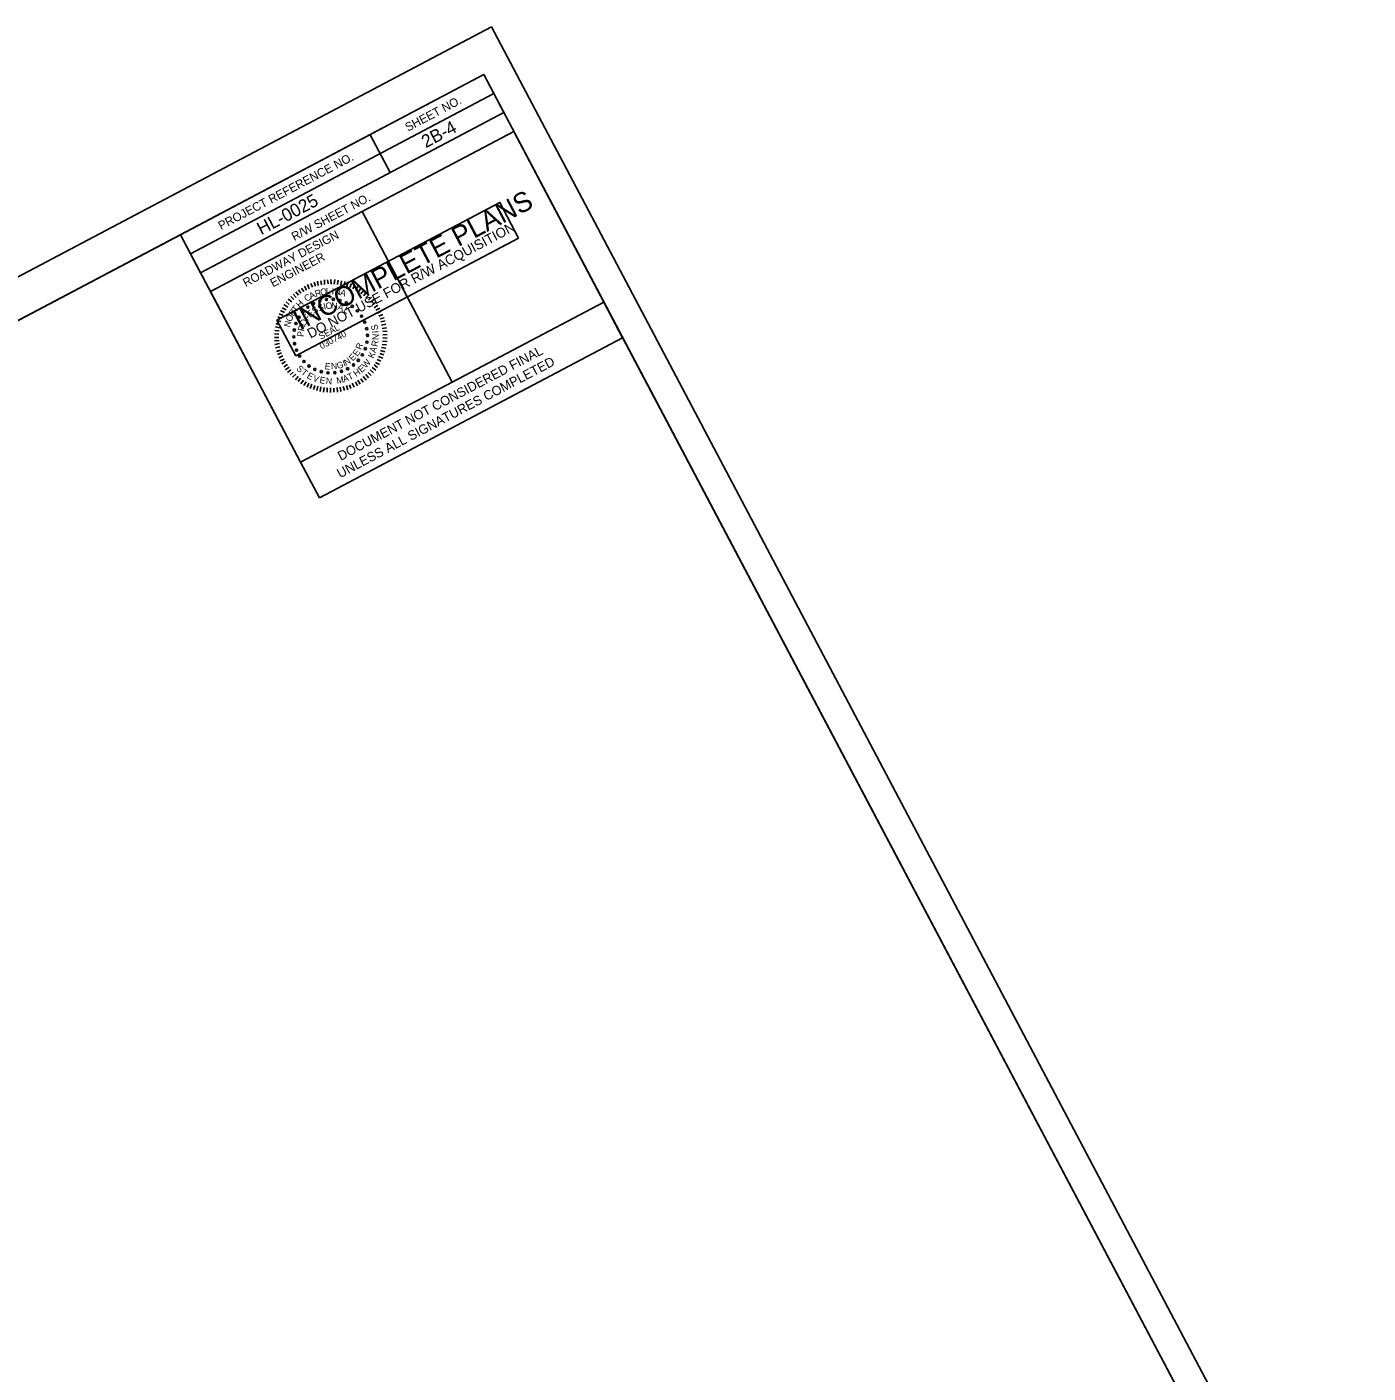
# Model space of a CAD drawing. Extents: x 1487555 to 1489555, y 497613 to 499367.
# Drawn here: x 1488773 to 1489555, y 498582 to 499367 of the extents above; entities that cross this region are included whole.
import ezdxf

# ---------------------------------------------------------------- set-up
doc = ezdxf.new("R2010")
doc.units = 0
for name, color, linetype in [('Old_Level_9', 7, 'Continuous'), ('Sheet Border Standard 30in CELL', 7, 'Continuous'), ('Sheet Data Field CELL', 7, 'Continuous'), ('Sheet Plan CELL', 7, 'Continuous'), ('Sheet Plot Border Outside CELL', 7, 'Continuous'), ('Sheet Sticker Exception Certification CELL', 7, 'Continuous'), ('Sheet Sticker Incomplete CELL', 7, 'Continuous')]:
    doc.layers.add(name, color=color, linetype=linetype)

msp = doc.modelspace()

# ---------------------------------------------------------------- linework, layer by layer
at = {"layer": 'Old_Level_9'}
for p, q in [((1488942.02, 499218.65), (1488942.52, 499216.2)), ((1488943.98, 499219), (1488944.48, 499216.55)), ((1488946.11, 499219.45), (1488946.17, 499216.77)), ((1488947.99, 499219.54), (1488948.27, 499217.09)), ((1488949.96, 499219.67), (1488950.02, 499216.99)), ((1488952.1, 499219.68), (1488951.8, 499217.03)), ((1488954.13, 499219.27), (1488953.73, 499216.8)), ((1488956.1, 499218.96), (1488955.62, 499216.44)), ((1488958.12, 499218.56), (1488957.55, 499216.22)), ((1488927.87, 499211.18), (1488929.65, 499209.29)), ((1488929.36, 499212.42), (1488930.92, 499210.53)), ((1488931.08, 499213.66), (1488932.38, 499211.63)), ((1488932.71, 499214.64), (1488934.1, 499212.66)), ((1488934.48, 499215.8), (1488935.69, 499213.5)), ((1488936.33, 499216.78), (1488937.28, 499214.34)), ((1488938.15, 499217.4), (1488939.1, 499215.18)), ((1488940.15, 499218.11), (1488940.83, 499215.76)), ((1488959.97, 499218.06), (1488959.26, 499215.54)), ((1488961.95, 499217.3), (1488961.02, 499215)), ((1488963.85, 499216.49), (1488962.65, 499214.27)), ((1488965.57, 499215.59), (1488964.37, 499213.37)), ((1488967.34, 499214.6), (1488966, 499212.42)), ((1488969.06, 499213.48), (1488967.45, 499211.38)), ((1488970.56, 499212.35), (1488969.18, 499210.26)), ((1488972.25, 499210.86), (1488970.32, 499208.94)), ((1488921.42, 499203.25), (1488923.78, 499202.01)), ((1488922.54, 499205.2), (1488924.73, 499203.64)), ((1488923.76, 499206.75), (1488925.63, 499205.13)), ((1488924.89, 499208.25), (1488927.07, 499206.69)), ((1488926.47, 499209.76), (1488928.21, 499207.96)), ((1488973.67, 499209.46), (1488971.78, 499207.68)), ((1488975, 499208.02), (1488973.02, 499206.41)), ((1488976.15, 499206.48), (1488974.26, 499204.91)), ((1488977.31, 499204.71), (1488975.15, 499203.23)), ((1488978.38, 499202.9), (1488976.16, 499201.74)), ((1488918.32, 499195.85), (1488920.71, 499195.18)), ((1488918.86, 499197.83), (1488921.16, 499196.89)), ((1488919.67, 499199.72), (1488922.06, 499198.61)), ((1488920.52, 499201.53), (1488922.78, 499200.46)), ((1488979.26, 499201.22), (1488977.05, 499200.05)), ((1488980.15, 499199.32), (1488977.94, 499198.37)), ((1488980.96, 499197.37), (1488978.6, 499196.69)), ((1488981.58, 499195.55), (1488979.04, 499195)), ((1488916.93, 499187.99), (1488919.48, 499187.86)), ((1488917.16, 499189.91), (1488919.71, 499189.79)), ((1488917.51, 499192.03), (1488919.94, 499191.5)), ((1488917.74, 499193.95), (1488920.21, 499193.34)), ((1488982.03, 499193.63), (1488979.49, 499193.09)), ((1488982.43, 499191.59), (1488979.71, 499191.17)), ((1488982.66, 499189.44), (1488980.15, 499189.48)), ((1488982.74, 499187.57), (1488980.28, 499187.51)), ((1488916.93, 499185.84), (1488919.62, 499185.9)), ((1488917.07, 499183.87), (1488919.66, 499184.11)), ((1488917.25, 499181.82), (1488919.92, 499182.33)), ((1488917.6, 499179.86), (1488920.14, 499180.41)), ((1488981.89, 499179.54), (1488979.46, 499180.07)), ((1488982.29, 499181.56), (1488979.78, 499181.82)), ((1488982.7, 499183.58), (1488980.01, 499183.75)), ((1488982.74, 499185.42), (1488980.15, 499185.63)), ((1488918.14, 499177.77), (1488920.59, 499178.49)), ((1488918.76, 499175.95), (1488921.11, 499176.85)), ((1488919.57, 499174), (1488921.91, 499175.12)), ((1488920.37, 499172.27), (1488922.67, 499173.26)), ((1488921.35, 499170.41), (1488923.46, 499171.76)), ((1488978.3, 499170.07), (1488975.94, 499171.31)), ((1488979.11, 499171.96), (1488976.85, 499173.03)), ((1488980.1, 499173.73), (1488977.61, 499174.79)), ((1488980.77, 499175.67), (1488978.51, 499176.51)), ((1488981.4, 499177.47), (1488978.92, 499178.31)), ((1488922.37, 499168.69), (1488924.53, 499170.17)), ((1488923.48, 499167.02), (1488925.5, 499168.54)), ((1488924.68, 499165.39), (1488926.61, 499167.09)), ((1488926.1, 499163.99), (1488927.94, 499165.64)), ((1488927.6, 499162.64), (1488929.4, 499164.38)), ((1488971.85, 499162.36), (1488970.2, 499164.21)), ((1488973.34, 499163.61), (1488971.69, 499165.45)), ((1488974.78, 499165.16), (1488972.73, 499166.9)), ((1488976.09, 499166.75), (1488974, 499168.36)), ((1488977.17, 499168.34), (1488975.13, 499169.86)), ((1488929.24, 499161.24), (1488930.72, 499163.15)), ((1488930.75, 499160.11), (1488932.18, 499162.11)), ((1488932.43, 499158.85), (1488933.9, 499160.99)), ((1488934.06, 499157.9), (1488935.4, 499160.08)), ((1488936.05, 499156.92), (1488937.07, 499159.27)), ((1488937.86, 499156.06), (1488938.7, 499158.54)), ((1488939.66, 499155.43), (1488940.55, 499157.82)), ((1488941.73, 499154.94), (1488942.26, 499157.37)), ((1488943.57, 499154.45), (1488944.01, 499157.05)), ((1488945.6, 499154.04), (1488945.94, 499156.6)), ((1488947.7, 499153.91), (1488947.82, 499156.46)), ((1488949.67, 499153.82), (1488949.66, 499156.42)), ((1488951.68, 499153.87), (1488951.63, 499156.32)), ((1488953.74, 499154.05), (1488953.5, 499156.63)), ((1488955.74, 499154.31), (1488955.33, 499156.81)), ((1488957.79, 499154.94), (1488957.11, 499157.3)), ((1488959.7, 499155.39), (1488958.98, 499157.83)), ((1488961.52, 499156.01), (1488960.67, 499158.27)), ((1488963.47, 499156.81), (1488962.35, 499159.16)), ((1488965.38, 499157.7), (1488964.21, 499159.91)), ((1488967.01, 499158.68), (1488965.62, 499160.88)), ((1488968.69, 499159.79), (1488967.3, 499161.77)), ((1488970.4, 499161.04), (1488968.79, 499163.01))]:
    msp.add_line(p, q, dxfattribs=at)
for centre in [(1488936.47, 499203.55), (1488939.8, 499205.7), (1488943.47, 499207.21), (1488947.35, 499208.01), (1488951.32, 499208.09), (1488955.23, 499207.44), (1488958.95, 499206.08), (1488962.37, 499204.06), (1488931.27, 499197.61), (1488933.59, 499200.82), (1488965.35, 499201.45), (1488967.8, 499198.33), (1488969.64, 499194.82), (1488928.56, 499190.19), (1488929.57, 499194.02), (1488970.8, 499191.03), (1488971.24, 499187.09), (1488928.28, 499186.23), (1488928.72, 499182.29), (1488969.95, 499179.3), (1488970.96, 499183.13), (1488929.88, 499178.5), (1488931.72, 499174.99), (1488934.17, 499171.87), (1488965.93, 499172.5), (1488968.25, 499175.72), (1488937.15, 499169.26), (1488940.57, 499167.24), (1488944.29, 499165.88), (1488948.2, 499165.23), (1488952.17, 499165.31), (1488956.05, 499166.11), (1488959.72, 499167.62), (1488963.05, 499169.77)]:
    msp.add_circle(centre, 0.63, dxfattribs=at)
at = {"layer": 'Sheet Border Standard 30in CELL'}
msp.add_line((1488873.82, 499223.66), (1488879.66, 499212.6), dxfattribs=at)
at = {"layer": 'Sheet Plan CELL'}
for p, q in [((1488867.98, 499234.72), (1489044.89, 499328.12)), ((1488873.85, 499223.64), (1489050.73, 499317.06)), ((1488873.85, 499223.64), (1489050.73, 499317.06)), ((1488972.71, 499304.13), (1488984.43, 499282.05)), ((1488968.15, 499259.31), (1489020.67, 499159.87)), ((1488873.85, 499223.64), (1488879.68, 499212.6))]:
    msp.add_line(p, q, dxfattribs=at)
for points in [[(1489039.06, 499339.23), (1487712.59, 498638.82), (1488202.86, 497710.31), (1489529.32, 498410.71)], [(1488862.13, 499245.82), (1489039.06, 499339.23), (1489050.73, 499317.06), (1488873.85, 499223.64)], [(1488968.15, 499259.31), (1489056.56, 499306.01), (1489109.11, 499206.52), (1489020.69, 499159.82)], [(1488879.68, 499212.6), (1488968.15, 499259.31), (1489020.69, 499159.82), (1488932.21, 499113.13)], [(1488202.86, 497710.31), (1487712.58, 498638.79), (1488862.13, 499245.82), (1488932.21, 499113.13), (1489109.11, 499206.52), (1489529.32, 498410.71)]]:
    msp.add_lwpolyline(points, close=True, dxfattribs=at)
at = {"layer": 'Sheet Plot Border Outside CELL'}
msp.add_lwpolyline([(1488066.15, 497612.67), (1489554.86, 498398.74), (1489043.57, 499367.04), (1487554.86, 498580.97)], close=True, dxfattribs=at)
at = {"layer": 'Sheet Sticker Exception Certification CELL'}
for p, q in [((1488932.21, 499113.13), (1489109.1, 499206.53)), ((1488932.21, 499113.13), (1489109.1, 499206.53)), ((1489109.11, 499206.52), (1489120.08, 499185.74)), ((1489109.11, 499206.52), (1489120.08, 499185.74)), ((1489120.08, 499185.75), (1488943.18, 499092.35)), ((1489120.08, 499185.75), (1488943.18, 499092.35)), ((1488943.18, 499092.35), (1488932.21, 499113.13)), ((1488943.18, 499092.35), (1488932.21, 499113.13))]:
    msp.add_line(p, q, dxfattribs=at)
at = {"layer": 'Sheet Sticker Incomplete CELL'}
msp.add_lwpolyline([(1488929.42, 499175.25), (1488918.45, 499196.03), (1489048.44, 499264.67), (1489059.41, 499243.89)], close=True, dxfattribs=at)

# ---------------------------------------------------------------- texts
at = {"layer": 'Old_Level_9'}
for s, height, rotation, p in [('C', 3.78, 32.77501, (1488935.75, 499206.52)), ('A', 3.78, 25.80995, (1488938.23, 499208.05)), ('R', 3.78, 17.85665, (1488941.24, 499209.42)), ('O', 3.78, 10.92189, (1488944.04, 499210.33)), ('L', 3.78, 3.581, (1488947.11, 499210.93)), ('I', 3.78, 358.64105, (1488950.33, 499211.05)), ('N', 3.78, 352.73893, (1488951.8, 499211.04)), ('A', 3.78, 344.84016, (1488954.9, 499210.52)), ('T', 3.78, 53.27087, (1488929.68, 499200.26)), ('H', 3.78, 45.57844, (1488931.76, 499202.94)), ('S', 3.76, 32.30312, (1488940.21, 499199.37)), ('S', 3.76, 20.87655, (1488942.99, 499200.95)), ('I', 3.76, 13.31716, (1488946.01, 499202.1)), ('O', 3.76, 5.70998, (1488946.99, 499202.39)), ('N', 3.76, 355.22811, (1488949.89, 499202.67)), ('A', 3.76, 341.77886, (1488953.52, 499202.22)), ('L', 3.76, 329.3674, (1488956.9, 499200.95)), ('N', 3.78, 75.90175, (1488926.02, 499191.54)), ('O', 3.78, 67.77931, (1488926.8, 499194.78)), ('R', 3.78, 60.01054, (1488928.21, 499197.9)), ('O', 3.76, 66.08691, (1488934.91, 499192.05)), ('F', 3.76, 54.23505, (1488936.5, 499195.26)), ('E', 3.76, 44.42402, (1488937.93, 499197.26)), ('P', 3.76, 87.95873, (1488934.06, 499186.17)), ('R', 3.76, 77.58289, (1488934.26, 499189.22)), ('SEAL', 3.759, 27.83509, (1488944.06, 499184.48)), ('030740', 3.759, 27.83509, (1488944.53, 499178.9)), ('S', 3.78, 100.09298, (1488977.51, 499190.36)), ('I', 3.78, 93.88149, (1488977.68, 499188.54)), ('N', 3.78, 87.20766, (1488977.75, 499184.28)), ('E', 3.76, 54.9919, (1488965.32, 499174.52)), ('R', 3.76, 68.18435, (1488967.56, 499178.42)), ('A', 3.78, 71.35678, (1488975.89, 499176.61)), ('R', 3.78, 78.98541, (1488977.09, 499180.26)), ('G', 3.76, 15.31634, (1488953.89, 499167.47)), ('I', 3.76, 23.45968, (1488957.75, 499168.72)), ('N', 3.76, 30.96288, (1488958.81, 499169.28)), ('E', 3.76, 43.64078, (1488962.56, 499171.82)), ('W', 3.78, 49.84085, (1488970.4, 499167.57)), ('K', 3.78, 63.9761, (1488974.63, 499173.38)), ('S', 3.78, 316.0471, (1488929.46, 499167.37)), ('T', 3.78, 323.45948, (1488932.15, 499164.81)), ('E', 3.78, 331.65758, (1488935.52, 499162.43)), ('V', 3.78, 339.76489, (1488939.01, 499160.67)), ('E', 3.76, 352.70428, (1488946.1, 499167.43)), ('N', 3.76, 3.89345, (1488950.05, 499167.25)), ('A', 3.78, 18.01726, (1488957.4, 499159.72)), ('T', 3.78, 25.22168, (1488960.68, 499160.82)), ('H', 3.78, 33.84631, (1488964.58, 499162.75)), ('E', 3.78, 41.99985, (1488967.79, 499165.11)), ('E', 3.78, 348.06633, (1488942.95, 499159.4)), ('N', 3.78, 356.16408, (1488946.85, 499158.71)), ('M', 3.78, 10.17213, (1488953.48, 499158.82))]:
    msp.add_text(s, height=height, rotation=rotation, dxfattribs=at).set_placement(p)
at = {"layer": 'Sheet Data Field CELL'}
for s, p in [('2B-4', (1489005.25, 499296.22)), ('HL-0025', (1488909.26, 499245.46))]:
    msp.add_text(s, height=7.5, rotation=27.8351, dxfattribs=at).set_placement(p)
at = {"layer": 'Sheet Plan CELL'}
for s, height, p in [('SHEET NO.', 5, (1488994.8, 499305.88)), ('PROJECT REFERENCE NO.', 5.0001, (1488885.84, 499248.47)), ('R/W SHEET NO.', 5.0001, (1488928.54, 499242.13)), ('ROADWAY DESIGN', 5.0001, (1488900.22, 499215.19)), ('ENGINEER', 5, (1488916.11, 499215.05))]:
    msp.add_text(s, height=height, rotation=27.8351, dxfattribs=at).set_placement(p)
at = {"layer": 'Sheet Sticker Exception Certification CELL'}
for s, p in [('DOCUMENT NOT CONSIDERED FINAL', (1488955.67, 499113.82)), ('DOCUMENT NOT CONSIDERED FINAL', (1488955.67, 499113.82)), ('UNLESS ALL SIGNATURES COMPLETED', (1488955.3, 499103.67)), ('UNLESS ALL SIGNATURES COMPLETED', (1488955.3, 499103.67))]:
    msp.add_text(s, height=5.5, rotation=27.83509, dxfattribs=at).set_placement(p)
at = {"layer": 'Sheet Sticker Incomplete CELL'}
for s, height, p in [('INCOMPLETE PLANS', 11.52, (1488931.87, 499189.78)), ('DO NOT USE FOR R/W ACQUISITION', 5.76, (1488937.99, 499185.15))]:
    msp.add_text(s, height=height, rotation=27.83509, dxfattribs=at).set_placement(p)

doc.saveas('drawing.dxf')
